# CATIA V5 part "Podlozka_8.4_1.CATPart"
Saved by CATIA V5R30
Part number: Podlozka_8.4_1
Definition: DIN 6340-8.4_2
Nomenclature: DIN 6340-8.4_2
Source: Unknown
Description: PART--DESC
Bounding box of the stored display mesh (mm): x -138.5 to -120.5, y 9.5 to 27.5, z 83.7 to 86.2
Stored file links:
  E:\Bakalarka\Model\Forma_v7\Podlozka_8.4_1.CATPart
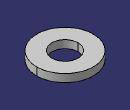
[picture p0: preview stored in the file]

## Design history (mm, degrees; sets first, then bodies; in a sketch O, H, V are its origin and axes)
Body1 "MANIFOLD_SOLID_BREP #3650" (main body)
  Solid1: solid without history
